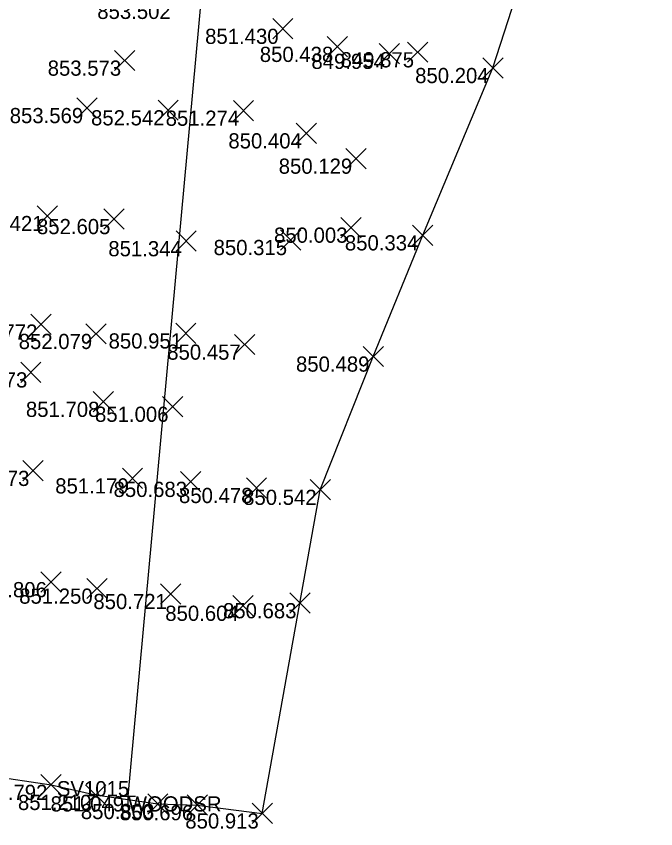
# Model space of a CAD drawing. Extents: x 2228183 to 2230895, y 679226 to 682223.
# Drawn here: x 2228326.7 to 2228368.8, y 680381.1 to 680434.6 of the extents above; entities that cross this region are included whole.
import ezdxf

# ---------------------------------------------------------------- set-up
doc = ezdxf.new("R2010")
doc.units = 0
for name, color, linetype in [('SC_Scratch1', 7, 'Continuous'), ('SV_P_Control_Cells_Set', 7, 'Continuous'), ('SV_X_Random_Point', 7, 'Continuous'), ('SV_X_Shot_Marker', 7, 'Continuous'), ('SV_X_Terrain_Boundary', 7, 'Continuous'), ('SV_X_Text_Comment', 7, 'Continuous'), ('VG_X_Tree_Line_Rt', 7, 'Continuous')]:
    doc.layers.add(name, color=color, linetype=linetype)

msp = doc.modelspace()

# ---------------------------------------------------------------- linework, layer by layer
at = {"layer": 'SV_X_Random_Point'}
for p, q in [((2228343.581, 680433.101), (2228344.915, 680434.436)), ((2228343.581, 680434.436), (2228344.915, 680433.101)), ((2228347.164, 680431.912), (2228348.498, 680433.247)), ((2228347.164, 680433.247), (2228348.498, 680431.912)), ((2228350.583, 680431.454), (2228351.917, 680432.789)), ((2228350.583, 680432.789), (2228351.917, 680431.454)), ((2228352.449, 680431.557), (2228353.783, 680432.892)), ((2228352.449, 680432.892), (2228353.783, 680431.557)), ((2228333.172, 680431.007), (2228334.506, 680432.342)), ((2228333.172, 680432.342), (2228334.506, 680431.007)), ((2228357.408, 680430.519), (2228358.742, 680431.854)), ((2228357.408, 680431.854), (2228358.742, 680430.519)), ((2228330.694, 680427.884), (2228332.028, 680429.219)), ((2228330.694, 680429.219), (2228332.028, 680427.884)), ((2228336.034, 680427.737), (2228337.368, 680429.072)), ((2228336.034, 680429.072), (2228337.368, 680427.737)), ((2228340.992, 680427.71), (2228342.326, 680429.045)), ((2228340.992, 680429.045), (2228342.326, 680427.71)), ((2228345.119, 680426.22), (2228346.453, 680427.555)), ((2228345.119, 680427.555), (2228346.453, 680426.22)), ((2228348.394, 680424.553), (2228349.728, 680425.888)), ((2228348.394, 680425.888), (2228349.728, 680424.553)), ((2228328.082, 680420.775), (2228329.416, 680422.11)), ((2228328.082, 680422.11), (2228329.416, 680420.775)), ((2228332.471, 680420.576), (2228333.805, 680421.911)), ((2228332.471, 680421.911), (2228333.805, 680420.576)), ((2228348.065, 680420.01), (2228349.399, 680421.345)), ((2228348.065, 680421.345), (2228349.399, 680420.01)), ((2228337.219, 680419.119), (2228338.553, 680420.454)), ((2228337.219, 680420.454), (2228338.553, 680419.119)), ((2228344.094, 680419.197), (2228345.428, 680420.532)), ((2228344.094, 680420.532), (2228345.428, 680419.197)), ((2228352.784, 680419.505), (2228354.118, 680420.84)), ((2228352.784, 680420.84), (2228354.118, 680419.505)), ((2228327.667, 680413.63), (2228329.001, 680414.965)), ((2228327.667, 680414.965), (2228329.001, 680413.63)), ((2228331.284, 680413.013), (2228332.618, 680414.348)), ((2228331.284, 680414.348), (2228332.618, 680413.013)), ((2228337.197, 680413.046), (2228338.531, 680414.381)), ((2228337.197, 680414.381), (2228338.531, 680413.046)), ((2228341.07, 680412.311), (2228342.404, 680413.646)), ((2228341.07, 680413.646), (2228342.404, 680412.311)), ((2228349.529, 680411.523), (2228350.863, 680412.858)), ((2228349.529, 680412.858), (2228350.863, 680411.523)), ((2228326.998, 680410.482), (2228328.332, 680411.817)), ((2228326.998, 680411.817), (2228328.332, 680410.482)), ((2228331.776, 680408.544), (2228333.11, 680409.879)), ((2228331.776, 680409.879), (2228333.11, 680408.544)), ((2228336.327, 680408.22), (2228337.661, 680409.555)), ((2228336.327, 680409.555), (2228337.661, 680408.22)), ((2228327.134, 680403.998), (2228328.468, 680405.333)), ((2228327.134, 680405.333), (2228328.468, 680403.998)), ((2228333.689, 680403.503), (2228335.023, 680404.838)), ((2228333.689, 680404.838), (2228335.023, 680403.503)), ((2228337.507, 680403.274), (2228338.841, 680404.609)), ((2228337.507, 680404.609), (2228338.841, 680403.274)), ((2228341.848, 680402.872), (2228343.182, 680404.207)), ((2228341.848, 680404.207), (2228343.182, 680402.872)), ((2228346.04, 680402.751), (2228347.374, 680404.086)), ((2228346.04, 680404.086), (2228347.374, 680402.751)), ((2228328.323, 680396.673), (2228329.657, 680398.008)), ((2228328.323, 680398.008), (2228329.657, 680396.673)), ((2228331.348, 680396.248), (2228332.682, 680397.583)), ((2228331.348, 680397.583), (2228332.682, 680396.248)), ((2228336.195, 680395.892), (2228337.529, 680397.227)), ((2228336.195, 680397.227), (2228337.529, 680395.892)), ((2228340.965, 680395.117), (2228342.299, 680396.452)), ((2228340.965, 680396.452), (2228342.299, 680395.117)), ((2228344.707, 680395.286), (2228346.041, 680396.621)), ((2228344.707, 680396.621), (2228346.041, 680395.286)), ((2228328.326, 680383.325), (2228329.66, 680384.66)), ((2228328.326, 680384.66), (2228329.66, 680383.325)), ((2228331.264, 680382.665), (2228332.598, 680384)), ((2228331.264, 680384), (2228332.598, 680382.665)), ((2228335.355, 680382.068), (2228336.689, 680383.403)), ((2228335.355, 680383.403), (2228336.689, 680382.068)), ((2228337.948, 680381.989), (2228339.282, 680383.324)), ((2228337.948, 680383.324), (2228339.282, 680381.989)), ((2228342.226, 680381.446), (2228343.56, 680382.781)), ((2228342.226, 680382.781), (2228343.56, 680381.446))]:
    msp.add_line(p, q, dxfattribs=at)
at = {"layer": 'SV_X_Shot_Marker'}
for p, q in [((2228334.048, 680383.735), (2228334.048, 680382.735)), ((2228333.548, 680383.235), (2228334.548, 680383.235)), ((2228334.048, 680383.235), (2228334.048, 680383.235))]:
    msp.add_line(p, q, dxfattribs=at)
at = {"layer": 'SV_X_Terrain_Boundary'}
msp.add_lwpolyline([(2228290.359, 680391.22), (2228294.777, 680389.962), (2228298.646, 680389.665), (2228303.563, 680389.056), (2228308.352, 680388.11), (2228316.318, 680386.57), (2228319.496, 680385.705), (2228324.89, 680384.604), (2228328.993, 680383.992), (2228331.931, 680383.332), (2228336.022, 680382.735), (2228338.615, 680382.656), (2228342.893, 680382.113), (2228346.707, 680403.418), (2228350.196, 680412.19), (2228353.451, 680420.172), (2228358.075, 680431.186), (2228359.828, 680436.631)], dxfattribs=at)
at = {"layer": 'VG_X_Tree_Line_Rt'}
msp.add_lwpolyline([(2228410.452, 680773.345), (2228402.142, 680728.483), (2228403.602, 680691.208), (2228374.606, 680596.133), (2228370.969, 680582.119), (2228367.614, 680567.008), (2228346.3, 680486.661), (2228340.655, 680455.186), (2228334.048, 680383.235)], dxfattribs=at)

# ---------------------------------------------------------------- texts
at = {"layer": 'SC_Scratch1'}
for s, p in [('853.502', (2228332.037, 680434.41)), ('851.430', (2228339.134, 680432.768)), ('850.438', (2228342.731, 680431.579)), ('849.875', (2228348.046, 680431.224)), ('853.573', (2228328.775, 680430.674)), ('849.954', (2228346.128, 680431.121)), ('850.204', (2228352.953, 680430.186)), ('853.569', (2228326.277, 680427.551)), ('852.542', (2228331.628, 680427.404)), ('851.274', (2228336.537, 680427.377)), ('850.404', (2228340.664, 680425.887)), ('850.129', (2228343.977, 680424.22)), ('853.421', (2228323.667, 680420.442)), ('852.605', (2228328.068, 680420.243)), ('850.003', (2228343.668, 680419.677)), ('850.334', (2228348.329, 680419.172)), ('851.344', (2228332.764, 680418.786)), ('850.315', (2228339.691, 680418.864)), ('852.772', (2228323.261, 680413.297)), ('852.079', (2228326.867, 680412.68)), ('850.951', (2228332.782, 680412.713)), ('850.457', (2228336.641, 680411.978)), ('850.489', (2228345.112, 680411.19)), ('852.573', (2228322.601, 680410.149)), ('851.708', (2228327.343, 680408.211)), ('851.006', (2228331.89, 680407.887)), ('852.273', (2228322.737, 680403.665)), ('851.179', (2228329.272, 680403.17)), ('850.683', (2228333.11, 680402.941)), ('850.478', (2228337.415, 680402.539)), ('850.542', (2228341.634, 680402.418)), ('851.806', (2228323.886, 680396.34)), ('851.250', (2228326.901, 680395.915)), ('850.721', (2228331.78, 680395.559)), ('850.683', (2228340.31, 680394.953)), ('850.604', (2228336.51, 680394.784)), ('851.792', (2228323.92, 680382.992)), ('851.210', (2228326.817, 680382.332)), ('851.049', (2228328.964, 680382.235)), ('850.803', (2228330.958, 680381.735)), ('850.696', (2228333.511, 680381.656)), ('850.913', (2228337.829, 680381.113))]:
    msp.add_text(s, height=1, dxfattribs=at).set_placement(p)
at = {"layer": 'SV_P_Control_Cells_Set'}
msp.add_text('SV1015', height=1, dxfattribs=at).set_placement((2228329.379, 680383.235))
at = {"layer": 'SV_X_Text_Comment'}
msp.add_text('WOODSR', height=1, dxfattribs=at).set_placement((2228334.048, 680382.235))

doc.saveas('drawing.dxf')
